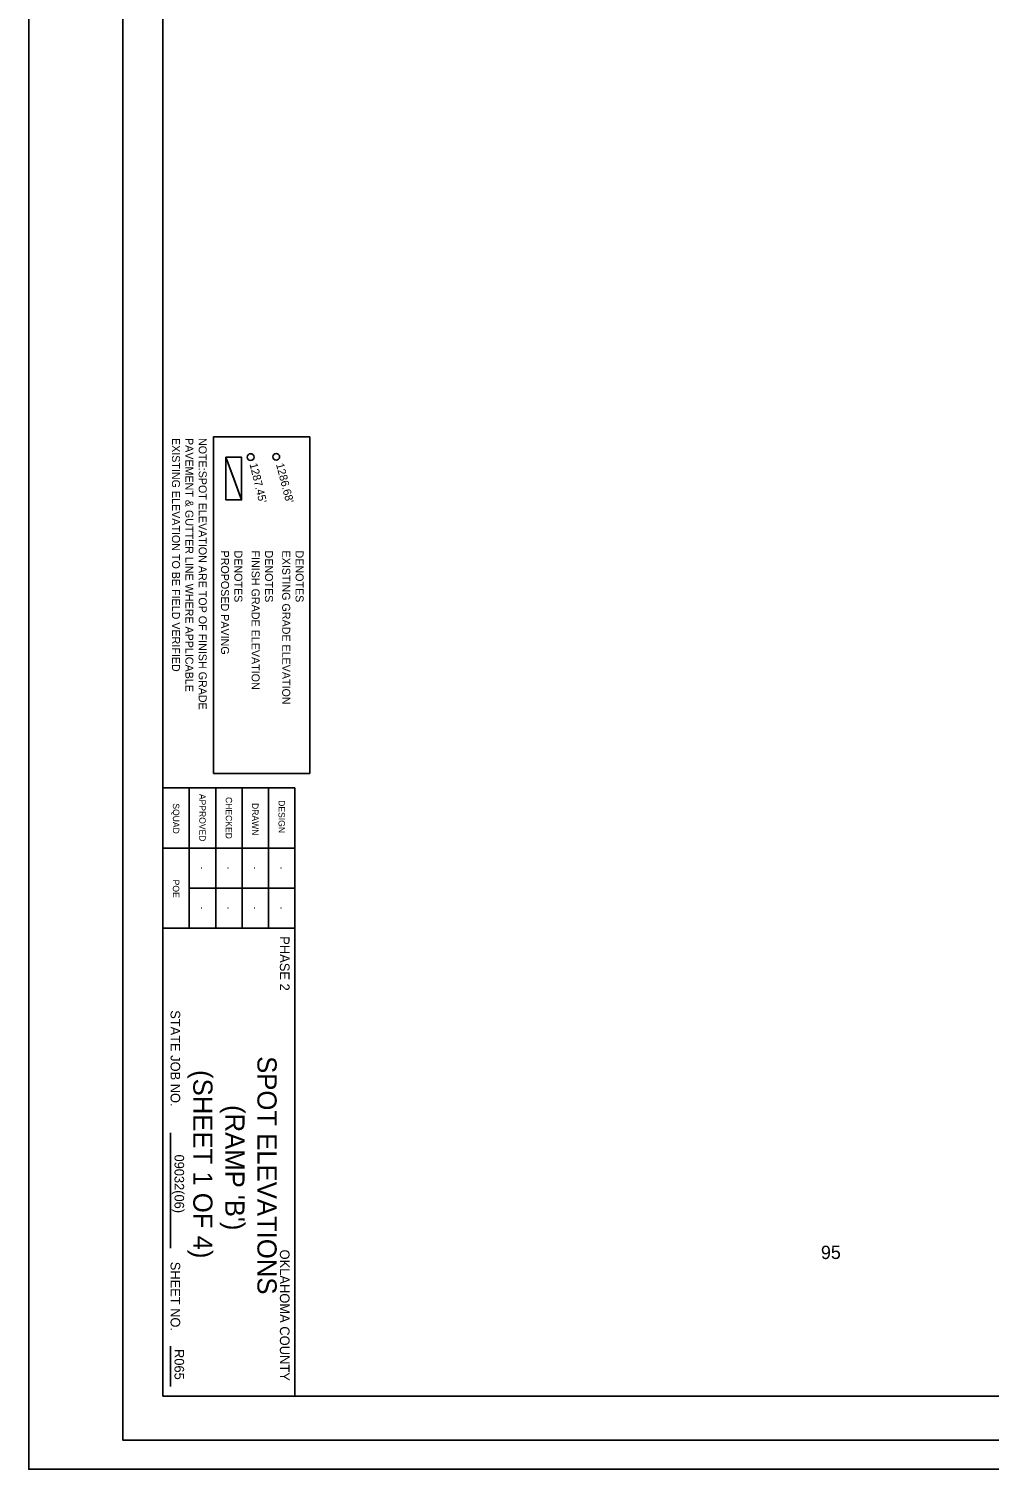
# Model space of a CAD drawing. Extents: x 2150486 to 2151206, y 144438 to 145518.
# Drawn here: x 2150486 to 2150846, y 144438 to 144978 of the extents above; entities that cross this region are included whole.
import ezdxf

# ---------------------------------------------------------------- set-up
doc = ezdxf.new("R2010")
doc.units = 0
for name, color, linetype in [('EX_Align_Sta', 7, 'Continuous'), ('EX_Align_Text', 7, 'Continuous'), ('INR_Tracking', 7, 'Continuous'), ('PR_Improvements_Txt', 7, 'Continuous'), ('PR_Misc_Improvement', 7, 'Continuous'), ('PR_Road_Concrete', 7, 'Continuous'), ('PR_Shading_1', 7, 'Continuous'), ('SHT_Plot_Shape_Half', 7, 'Continuous'), ('SHT_Sheet_Border', 7, 'Continuous'), ('SHT_Standard_Sheet_Txt', 7, 'Continuous'), ('TOPO_Curb Gut', 7, 'Continuous'), ('TOPO_Fence', 7, 'Continuous'), ('TOPO_RR Rail', 7, 'Continuous')]:
    doc.layers.add(name, color=color, linetype=linetype)

msp = doc.modelspace()

# ---------------------------------------------------------------- linework, layer by layer
at = {"layer": 'PR_Improvements_Txt'}
for points in [[(2150591.66, 144824.73), (2150591.66, 144698.53), (2150555.56, 144698.53), (2150555.56, 144824.73)], [(2150566.06, 144817.07), (2150566.06, 144801.06), (2150560.23, 144801.06), (2150560.23, 144817.07)]]:
    msp.add_lwpolyline(points, close=True, dxfattribs=at)
at = {"layer": 'PR_Misc_Improvement'}
for centre in [(2150569.48, 144817.13), (2150579.08, 144817.23)]:
    msp.add_circle(centre, 1.27, dxfattribs=at)
at = {"layer": 'PR_Road_Concrete'}
msp.add_line((2150560.23, 144817.07), (2150566.06, 144801.06), dxfattribs=at)
at = {"layer": 'PR_Shading_1'}
msp.add_lwpolyline([(2150560.23, 144817.07), (2150563.14, 144809.07), (2150566.06, 144801.06), (2150566.06, 144817.07), (2150560.23, 144817.07)], dxfattribs=at)
at = {"layer": 'SHT_Plot_Shape_Half'}
msp.add_lwpolyline([(2151181.58, 145468.57), (2151181.58, 144448.57), (2150521.58, 144448.57), (2150521.58, 145468.57)], close=True, dxfattribs=at)
at = {"layer": 'SHT_Sheet_Border'}
for p, q in [((2150536.58, 144693.07), (2150586.08, 144693.07)), ((2150586.08, 144693.07), (2150586.08, 144465.07)), ((2150536.57, 144640.57), (2150586.1, 144640.57))]:
    msp.add_line(p, q, dxfattribs=at)
msp.add_lwpolyline([(2150536.58, 144465.07), (2150536.58, 145410.07), (2151166.58, 145410.07), (2151166.58, 144465.07)], close=True, dxfattribs=at)
at = {"layer": 'TOPO_Curb Gut'}
msp.add_lwpolyline([(2151206.32, 145517.69), (2151206.32, 144437.69), (2150486.32, 144437.69), (2150486.32, 145517.69)], close=True, dxfattribs=at)
at = {"layer": 'TOPO_Fence'}
for p, q in [((2150536.57, 144670.57), (2150586.1, 144670.57)), ((2150546.48, 144655.57), (2150586.1, 144655.57)), ((2150539.46, 144563.74), (2150539.46, 144520.53)), ((2150539.46, 144483.8), (2150539.46, 144468.73))]:
    msp.add_line(p, q, dxfattribs=at)
for points in [[(2150546.48, 144640.57), (2150546.48, 144693.07)], [(2150556.38, 144640.57), (2150556.38, 144693.07)], [(2150566.28, 144640.57), (2150566.28, 144693.07)], [(2150576.18, 144640.57), (2150576.18, 144693.07)]]:
    msp.add_lwpolyline(points, dxfattribs=at)
at = {"layer": 'TOPO_RR Rail'}
msp.add_lwpolyline([(2150566.06, 144801.06), (2150563.14, 144809.07), (2150560.23, 144817.07), (2150560.23, 144801.06), (2150566.06, 144801.06)], dxfattribs=at)

# ---------------------------------------------------------------- texts
at = {"layer": 'EX_Align_Sta'}
msp.add_text('95', height=5, rotation=0.3443, dxfattribs=at).set_placement((2150783.28, 144516.46))
at = {"layer": 'EX_Align_Text'}
msp.add_text("1286.68' ", height=3, rotation=284.6073, dxfattribs=at).set_placement((2150578.96, 144814.43))
at = {"layer": 'INR_Tracking'}
msp.add_text("1287.45' ", height=3, rotation=283.8066, dxfattribs=at).set_placement((2150569.04, 144814.49))
at = {"layer": 'PR_Improvements_Txt'}
for s, p in [('EXISTING ELEVATION TO BE FIELD VERIFIED', (2150539.99, 144824.28)), ('PAVEMENT & GUTTER LINE WHERE APPLICABLE', (2150545, 144824.28)), ('NOTE:SPOT ELEVATION ARE TOP OF FINISH GRADE', (2150550.01, 144824.28)), ('PROPOSED PAVING', (2150558.37, 144782.08)), ('DENOTES', (2150563.38, 144782.08)), ('FINISH GRADE ELEVATION', (2150569.84, 144782.08)), ('DENOTES', (2150574.85, 144782.08)), ('EXISTING GRADE ELEVATION', (2150581.31, 144782.08)), ('DENOTES', (2150586.32, 144782.08))]:
    msp.add_text(s, height=3, rotation=270, dxfattribs=at).set_placement(p)
at = {"layer": 'SHT_Standard_Sheet_Txt'}
for s, height, p in [('APPROVED', 2.4, (2150550.23, 144690.86)), ('CHECKED', 2.4, (2150560.13, 144689.68)), ('DESIGN', 2.4, (2150579.93, 144688.5)), ('SQUAD', 2.4, (2150540.33, 144687.32)), ('DRAWN', 2.4, (2150570.03, 144687.43)), ('-', 2.4, (2150550.21, 144663.65)), ('-', 2.4, (2150560.11, 144663.65)), ('-', 2.4, (2150570.01, 144663.65)), ('-', 2.4, (2150579.94, 144663.65)), ('POE', 2.4, (2150540.32, 144658.71)), ('-', 2.4, (2150550.21, 144648.65)), ('-', 2.4, (2150560.11, 144648.65)), ('-', 2.4, (2150570.01, 144648.65)), ('-', 2.4, (2150579.94, 144648.65)), ('PHASE 2', 3.621, (2150580.44, 144637.5)), ('STATE JOB NO.', 3.6, (2150539.46, 144609.75)), ('SPOT ELEVATIONS', 7.2, (2150572.02, 144592.54)), ('(SHEET 1 OF 4)', 7.2, (2150547.97, 144587.32)), ("(RAMP 'B')", 7.2, (2150559.99, 144574.21)), ('09032(06)', 3.6, (2150540.94, 144555.66)), ('SHEET NO. ', 3.6, (2150539.46, 144515.45)), ('OKLAHOMA COUNTY', 3.6211, (2150580.44, 144520.04)), ('R065', 3.6, (2150540.94, 144482.73))]:
    msp.add_text(s, height=height, rotation=270, dxfattribs=at).set_placement(p)

doc.saveas('drawing.dxf')
